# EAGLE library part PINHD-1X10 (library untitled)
PIN HEADER
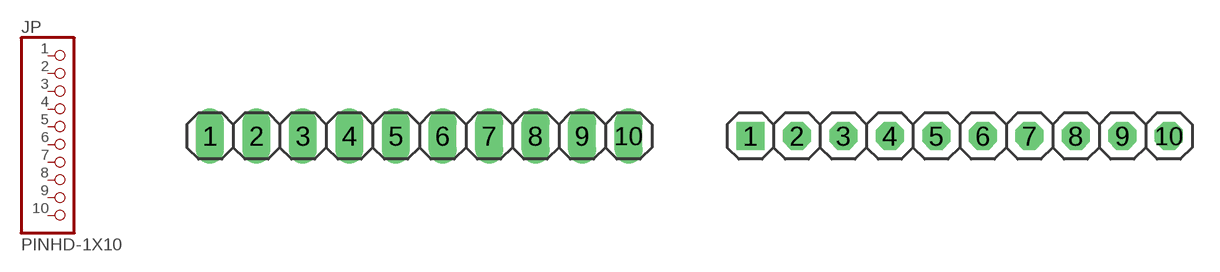
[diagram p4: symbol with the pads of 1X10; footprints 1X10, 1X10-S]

Designator prefix JP

## PINHD-1X10_2.54  [1X10]
1  1  pas
2  2  pas
3  3  pas
4  4  pas
5  5  pas
6  6  pas
7  7  pas
8  8  pas
9  9  pas
10  10  pas

## PINHD-1X10_2.54-S  [1X10-S]
Pads as for 1X10

## PINHD-1X10_2.54-90°  [1X10/90]
Pads as for 1X10

## PINHD-1X10_2.54-90°-S  [1X10/90-S]
Pads as for 1X10

## PINHD-1X10_2.00  [1X10M]
Pads as for 1X10

## PINHD-1X10_2.54-SMD  [1X10SMD]
Pads as for 1X10

## PINHD-1X10_2.54-SMD-90°  [1X10SMD/90]
Pads as for 1X10

## Footprint 1X10 (pad centres in mm)
PIN HEADER - 2.54
drill 1.016 long: 1 -11.43,0; 2 -8.89,0; 3 -6.35,0; 4 -3.81,0; 5 -1.27,0; 6 1.27,0; 7 3.81,0; 8 6.35,0; 9 8.89,0; 10 11.43,0

## Footprint 1X10-S (pad centres in mm)
PIN HEADER - 2.54
drill 1.016 square: 1 -11.43,0
drill 1.016 octagon: 2 -8.89,0; 3 -6.35,0; 4 -3.81,0; 5 -1.27,0; 6 1.27,0; 7 3.81,0; 8 6.35,0; 9 8.89,0; 10 11.43,0

## Footprint 1X10/90 (pad centres in mm)
PIN HEADER - 2.54 90°
drill 1.016 long: 1 -11.43,-3.81; 2 -8.89,-3.81; 3 -6.35,-3.81; 4 -3.81,-3.81; 5 -1.27,-3.81; 6 1.27,-3.81; 7 3.81,-3.81; 8 6.35,-3.81; 9 8.89,-3.81; 10 11.43,-3.81

## Footprint 1X10/90-S (pad centres in mm)
PIN HEADER - 2.54 90°
drill 1.016 square: 1 -11.43,-3.81
drill 1.016 octagon: 2 -8.89,-3.81; 3 -6.35,-3.81; 4 -3.81,-3.81; 5 -1.27,-3.81; 6 1.27,-3.81; 7 3.81,-3.81; 8 6.35,-3.81; 9 8.89,-3.81; 10 11.43,-3.81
